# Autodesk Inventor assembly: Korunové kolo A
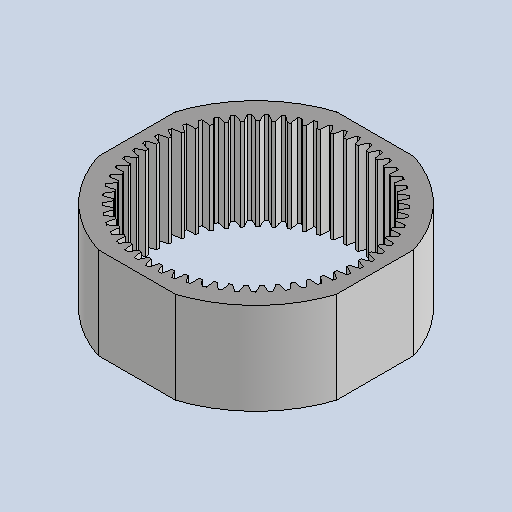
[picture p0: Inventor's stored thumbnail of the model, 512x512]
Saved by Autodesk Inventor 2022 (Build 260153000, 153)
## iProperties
Created: 2025-05
Part Number: Korunové kolo A
Document SubType Name: Assembly
Designer: jbart
Mass: 5402.18 g
Surface Area: 5816 cm^2
Volume: 5402.18 cm^3
Density: 1 g/cm^3
Author: jbart
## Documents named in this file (2)
- C:\Users\jbart\OneDrive\Dokumenty\Inventor\Převodovka navijáku\Korunové kolo 1.iam
- C:\Users\jbart\OneDrive\Dokumenty\Inventor\Převodovka navijáku\Korunové kolo 1\Design Accelerator\Čelní ozubená kola1.iam
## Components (1 placed, 1 different names)
1. Čelní ozubená kola:1 [sub-assembly]
